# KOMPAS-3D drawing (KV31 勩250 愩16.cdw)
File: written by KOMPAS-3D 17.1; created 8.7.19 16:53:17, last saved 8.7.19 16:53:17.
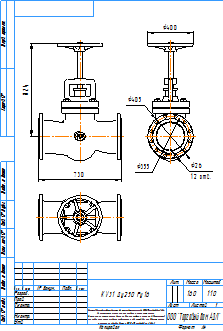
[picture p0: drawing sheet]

Sheet 1: A4, portrait

Title block, sheet 1: name: KV31 Ду250 Ру16; material: Сталь 10  ГОСТ 1050-88; mass: 160; sheets: 1; sheet format: A4

Views: Вид 1, Проекционный вид 2, Проекционный вид 3
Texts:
  kka
  adl
  Рама для чертежей
  Лит-Масса-Масштаб
  Материал-Предприятие
  Масштаб
  Изм.
  Лист
  № докум.
  Подп.
  Дата
  Лит.
  Разраб.
  Пров.
  Т.контр.
  Листов
  Внимание! Данный продукт является объектом авторского права ООО «Торговый Дом АДЛ».
  Запрещается изменение, копирование, распространение
  (в том числе путем копирования на другие сайты и ресурсы в Интернете)
  или любое иное использование информации и объектов без предварительного
  согласия правообладателя (ООО «Торговый Дом АДЛ»).
  Н.контр.
  Утв.
  ООО "Торговый дом АДЛ"
  Изменение
  Номер документа
  Подпись
  Обозначение документа
  Наименование изделия
  Масса изделия по ГОСТ 2.109-73
  Порядковый номер листа
  Общее количество листов в документе
  Характер работы, выполненной лицом, подписавшим документ
  Наименование или индекс предприятия, выпускающего документ
  Инв. № подл.
  Подп. и дата
  Взам. инв. №
  Инв. № дубл.
  Инвентарный номер подлинника по ГОСТ 2.501-68
  Подпись принявшего подлинник в отдел технической документации
  Инвентарный номер подлинника, взамен которого выпущен данный подлинник
  Инвентарный номер дубликата по ГОСТ 2.502-68
  Подпись принявшего дубликат в отдел технической документации
  Справ. №
  Перв. примен.
  Обозначение документа, взамен или на основании которого выпущен данный документ
  Обозначение документа, в котором впервые записан данный документ
  Подпись лица, копировавшего чертеж
  Обозначение формата листа
  !Рама для чертежа
Dimensions and other numbers on the sheet: 730; 824; 405; 26; 12 отв.; 355; 400; 1:10; 1; 160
